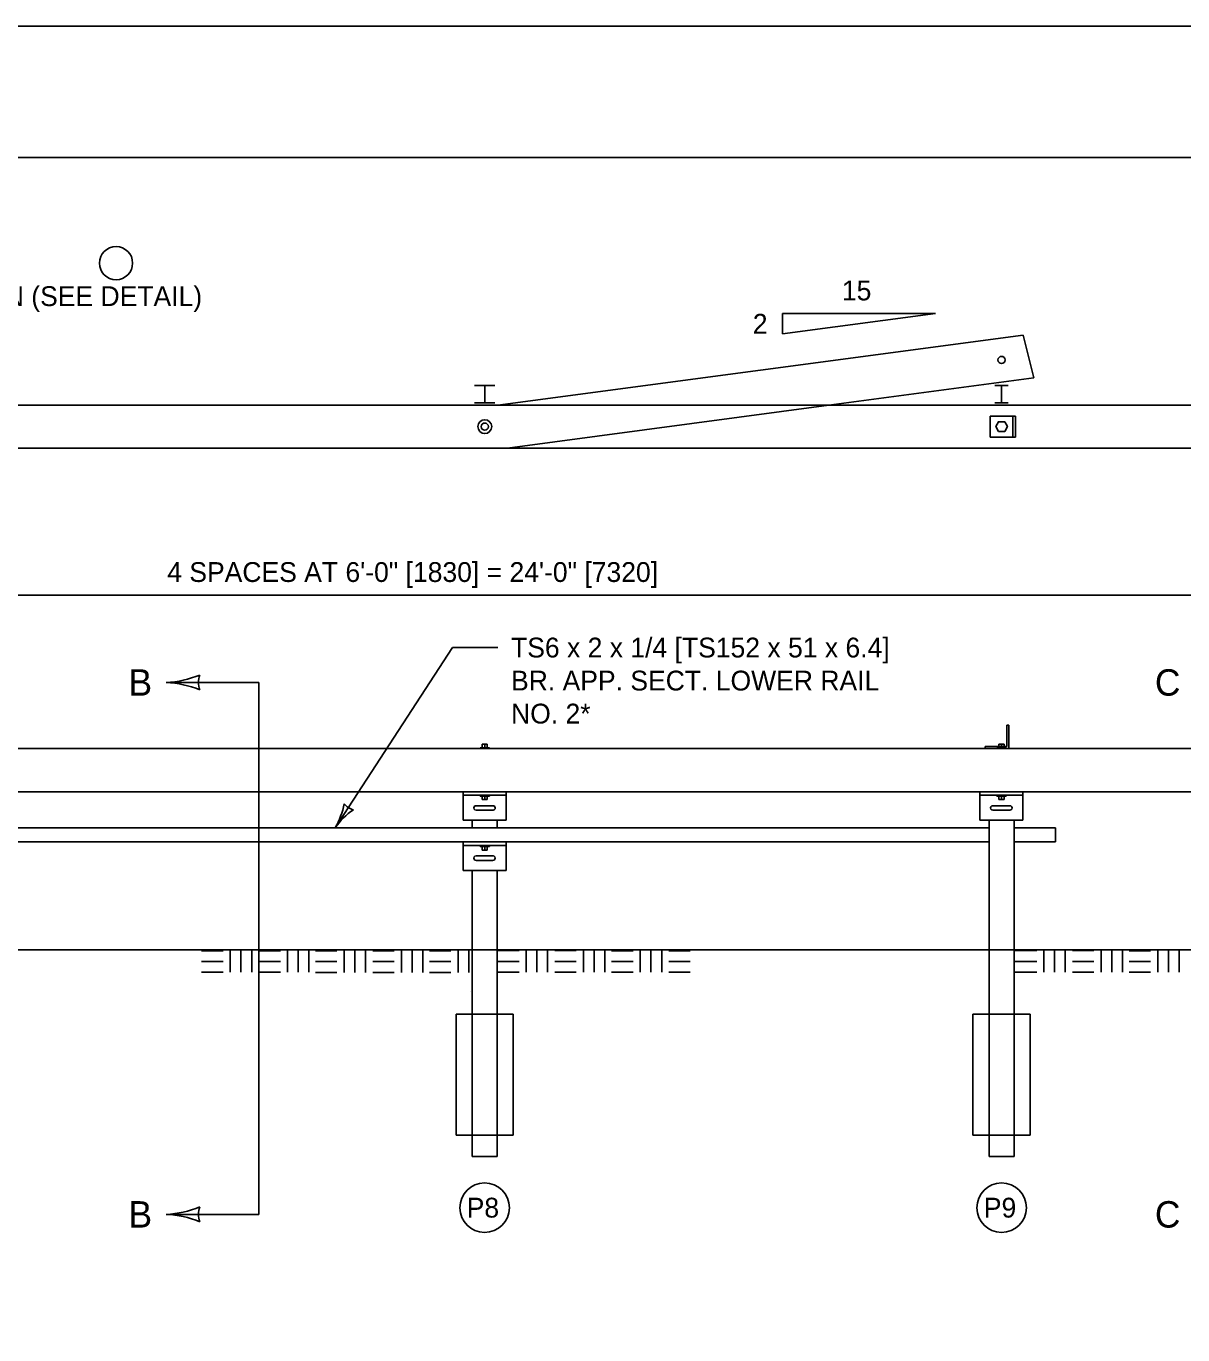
# Model space of a CAD drawing. Extents: x 49991.4 to 50021, y 49987.6 to 50011.4.
# Drawn here: x 50009.589 to 50013.09, y 49995.037 to 49998.999 of the extents above; entities that cross this region are included whole.
import ezdxf

# ---------------------------------------------------------------- set-up
doc = ezdxf.new("R2010")
doc.units = 0
for name, color, linetype in [('Level 1', 7, 'Continuous'), ('Level 2', 7, 'Continuous'), ('Level 3', 7, 'Continuous'), ('Level 4', 7, 'Continuous'), ('Level 6', 7, 'Continuous')]:
    doc.layers.add(name, color=color, linetype=linetype)

msp = doc.modelspace()

# ---------------------------------------------------------------- linework, layer by layer
at = {"layer": 'Level 1'}
for p, q in [((50011.0164, 49997.8514), (50012.6065, 49998.0634)), ((50012.6394, 49997.9343), (50012.6071, 49998.0636)), ((50012.0183, 49997.8514), (50012.6394, 49997.9343)), ((50010.9456, 49997.9109), (50011.0071, 49997.9109)), ((50010.9769, 49997.8585), (50010.9769, 49997.9109)), ((50012.5209, 49997.9109), (50012.5609, 49997.9109)), ((50012.5413, 49997.8585), (50012.5413, 49997.9109)), ((50001.743, 49997.8514), (50015.4519, 49997.8514)), ((50010.9456, 49997.8585), (50011.0071, 49997.8585)), ((50012.5209, 49997.8585), (50012.5609, 49997.8585)), ((50012.5067, 49997.818), (50012.5837, 49997.818)), ((50012.5068, 49997.7548), (50012.5068, 49997.818)), ((50012.5753, 49997.7548), (50012.5753, 49997.818)), ((50012.5839, 49997.7548), (50012.5839, 49997.818)), ((50012.5067, 49997.7548), (50012.5837, 49997.7548)), ((50001.743, 49997.7218), (50015.4519, 49997.7218)), ((50012.5574, 49996.8177), (50012.5574, 49996.8831)), ((50012.5574, 49996.8831), (50012.5633, 49996.8831)), ((50012.5633, 49996.8831), (50012.5633, 49996.8116)), ((50010.9688, 49996.825), (50010.9839, 49996.825)), ((50010.9688, 49996.825), (50010.9688, 49996.8144)), ((50010.9769, 49996.825), (50010.9769, 49996.8144)), ((50010.9839, 49996.825), (50010.9839, 49996.8144)), ((50012.4917, 49996.8118), (50012.4917, 49996.8177)), ((50012.4917, 49996.8177), (50012.5574, 49996.8177)), ((50012.5326, 49996.825), (50012.5494, 49996.825)), ((50012.5326, 49996.825), (50012.5326, 49996.8144)), ((50012.5413, 49996.825), (50012.5413, 49996.8144)), ((50012.5494, 49996.825), (50012.5494, 49996.8144)), ((50002.0298, 49996.8116), (50015.4519, 49996.8116)), ((50010.9439, 49996.8116), (50011.0087, 49996.8116)), ((50010.9625, 49996.8144), (50010.991, 49996.8144)), ((50010.9625, 49996.8116), (50010.9625, 49996.8144)), ((50010.991, 49996.8116), (50010.991, 49996.8144)), ((50012.5076, 49996.8116), (50012.5733, 49996.8116)), ((50012.5272, 49996.8144), (50012.5547, 49996.8144)), ((50012.5272, 49996.8116), (50012.5272, 49996.8144)), ((50012.5547, 49996.8116), (50012.5547, 49996.8144)), ((50002.0298, 49996.6812), (50015.4519, 49996.6812)), ((50010.9111, 49996.595), (50010.9111, 49996.6812)), ((50010.9111, 49996.6705), (50011.0416, 49996.6705)), ((50010.9625, 49996.6705), (50010.9625, 49996.6679)), ((50010.9625, 49996.6679), (50010.991, 49996.6679)), ((50010.9688, 49996.6572), (50010.9688, 49996.6679)), ((50010.9688, 49996.6572), (50010.9839, 49996.6572)), ((50010.9769, 49996.6572), (50010.9769, 49996.6679)), ((50010.9839, 49996.6572), (50010.9839, 49996.6679)), ((50010.991, 49996.6705), (50010.991, 49996.6679)), ((50011.0416, 49996.595), (50011.0416, 49996.6812)), ((50012.4757, 49996.595), (50012.4757, 49996.6812)), ((50012.4757, 49996.6705), (50012.6053, 49996.6705)), ((50012.5272, 49996.6705), (50012.5272, 49996.6679)), ((50012.5272, 49996.6679), (50012.5547, 49996.6679)), ((50012.5326, 49996.6572), (50012.5326, 49996.6679)), ((50012.5326, 49996.6572), (50012.5494, 49996.6572)), ((50012.5413, 49996.6572), (50012.5413, 49996.6679)), ((50012.5494, 49996.6572), (50012.5494, 49996.6679)), ((50012.5547, 49996.6705), (50012.5547, 49996.6679)), ((50012.6053, 49996.595), (50012.6053, 49996.6812)), ((50010.9498, 49996.6389), (50011.0021, 49996.6389)), ((50010.9506, 49996.6253), (50011.0023, 49996.6253)), ((50012.5144, 49996.6389), (50012.5667, 49996.6389)), ((50012.5153, 49996.6253), (50012.5659, 49996.6253)), ((50010.9111, 49996.595), (50011.0416, 49996.595)), ((50010.9386, 49996.5719), (50010.9386, 49996.5949)), ((50011.0142, 49996.5719), (50011.0142, 49996.5955)), ((50012.4757, 49996.595), (50012.6053, 49996.595)), ((50012.5032, 49996.2026), (50012.5032, 49996.595)), ((50012.5796, 49996.2026), (50012.5796, 49996.595)), ((50002.0449, 49996.5719), (50012.5032, 49996.5719)), ((50012.5796, 49996.5719), (50012.704, 49996.5719)), ((50012.704, 49996.5294), (50012.704, 49996.5719)), ((50007.0813, 49996.5294), (50012.5032, 49996.5294)), ((50010.9111, 49996.4422), (50010.9111, 49996.5294)), ((50010.9111, 49996.5187), (50011.0416, 49996.5187)), ((50010.9625, 49996.5187), (50010.9625, 49996.5152)), ((50010.9625, 49996.5152), (50010.991, 49996.5152)), ((50010.9688, 49996.5044), (50010.9688, 49996.5152)), ((50010.9688, 49996.5044), (50010.9839, 49996.5044)), ((50010.9769, 49996.5044), (50010.9769, 49996.5152)), ((50010.9839, 49996.5044), (50010.9839, 49996.5152)), ((50010.991, 49996.5187), (50010.991, 49996.5152)), ((50011.0416, 49996.4422), (50011.0416, 49996.5294)), ((50012.5796, 49996.5294), (50012.704, 49996.5294)), ((50010.9506, 49996.4868), (50011.0032, 49996.4868)), ((50010.9506, 49996.4732), (50011.0013, 49996.4732)), ((50010.9111, 49996.4422), (50011.0416, 49996.4422)), ((50010.9386, 49996.2026), (50010.9386, 49996.4422)), ((50011.0142, 49996.2026), (50011.0142, 49996.4428)), ((50001.5626, 49996.2026), (50015.4519, 49996.2026)), ((50010.1197, 49996.1996), (50010.1847, 49996.1996)), ((50010.2064, 49996.1346), (50010.2064, 49996.1996)), ((50010.2389, 49996.1346), (50010.2389, 49996.1996)), ((50010.2714, 49996.1346), (50010.2714, 49996.1996)), ((50010.293, 49996.1996), (50010.3581, 49996.1996)), ((50010.3798, 49996.1346), (50010.3798, 49996.1996)), ((50010.4122, 49996.1346), (50010.4122, 49996.1996)), ((50010.4447, 49996.1346), (50010.4447, 49996.1996)), ((50010.4645, 49996.1991), (50010.5295, 49996.1991)), ((50010.5512, 49996.1341), (50010.5512, 49996.1991)), ((50010.5837, 49996.1341), (50010.5837, 49996.1991)), ((50010.6162, 49996.1341), (50010.6162, 49996.1991)), ((50010.6378, 49996.1991), (50010.7029, 49996.1991)), ((50010.7246, 49996.1341), (50010.7246, 49996.1991)), ((50010.757, 49996.1341), (50010.757, 49996.1991)), ((50010.7895, 49996.1341), (50010.7895, 49996.1991)), ((50010.8092, 49996.1991), (50010.8742, 49996.1991)), ((50010.8959, 49996.1341), (50010.8959, 49996.1991)), ((50010.9284, 49996.1341), (50010.9284, 49996.1991)), ((50011.0155, 49996.2), (50011.0805, 49996.2)), ((50011.1022, 49996.135), (50011.1022, 49996.2)), ((50011.1347, 49996.135), (50011.1347, 49996.2)), ((50011.1672, 49996.135), (50011.1672, 49996.2)), ((50011.1888, 49996.2), (50011.2539, 49996.2)), ((50011.2756, 49996.135), (50011.2756, 49996.2)), ((50011.308, 49996.135), (50011.308, 49996.2)), ((50011.3405, 49996.135), (50011.3405, 49996.2)), ((50011.3607, 49996.1996), (50011.4257, 49996.1996)), ((50011.4474, 49996.1346), (50011.4474, 49996.1996)), ((50011.4799, 49996.1346), (50011.4799, 49996.1996)), ((50011.5124, 49996.1346), (50011.5124, 49996.1996)), ((50011.534, 49996.1996), (50011.5991, 49996.1996)), ((50012.5825, 49996.1999), (50012.6475, 49996.1999)), ((50012.6692, 49996.1349), (50012.6692, 49996.1999)), ((50012.7017, 49996.1349), (50012.7017, 49996.1999)), ((50012.7342, 49996.1349), (50012.7342, 49996.1999)), ((50012.7558, 49996.1999), (50012.8209, 49996.1999)), ((50012.8426, 49996.1349), (50012.8426, 49996.1999)), ((50012.875, 49996.1349), (50012.875, 49996.1999)), ((50012.9075, 49996.1349), (50012.9075, 49996.1999)), ((50012.9274, 49996.1995), (50012.9924, 49996.1995)), ((50013.0141, 49996.1345), (50013.0141, 49996.1995)), ((50013.0466, 49996.1345), (50013.0466, 49996.1995)), ((50013.0791, 49996.1345), (50013.0791, 49996.1995)), ((50010.1197, 49996.1671), (50010.1847, 49996.1671)), ((50010.293, 49996.1671), (50010.3581, 49996.1671)), ((50010.4645, 49996.1666), (50010.5295, 49996.1666)), ((50010.6378, 49996.1666), (50010.7029, 49996.1666)), ((50010.8092, 49996.1666), (50010.8742, 49996.1666)), ((50011.0155, 49996.1675), (50011.0805, 49996.1675)), ((50011.1888, 49996.1675), (50011.2539, 49996.1675)), ((50011.3607, 49996.1671), (50011.4257, 49996.1671)), ((50011.534, 49996.1671), (50011.5991, 49996.1671)), ((50012.5825, 49996.1674), (50012.6475, 49996.1674)), ((50012.7558, 49996.1674), (50012.8209, 49996.1674)), ((50012.9274, 49996.167), (50012.9924, 49996.167)), ((50010.1197, 49996.1346), (50010.1847, 49996.1346)), ((50010.293, 49996.1346), (50010.3581, 49996.1346)), ((50010.4645, 49996.1341), (50010.5295, 49996.1341)), ((50010.6378, 49996.1341), (50010.7029, 49996.1341)), ((50010.8092, 49996.1341), (50010.8742, 49996.1341)), ((50011.0155, 49996.135), (50011.0805, 49996.135)), ((50011.1888, 49996.135), (50011.2539, 49996.135)), ((50011.3607, 49996.1346), (50011.4257, 49996.1346)), ((50011.534, 49996.1346), (50011.5991, 49996.1346)), ((50012.5825, 49996.1349), (50012.6475, 49996.1349)), ((50012.7558, 49996.1349), (50012.8209, 49996.1349)), ((50012.9274, 49996.1345), (50012.9924, 49996.1345))]:
    msp.add_line(p, q, dxfattribs=at)
for points in [[(49999.3835, 49998.9992), (50016.7501, 49998.9992), (50016.7501, 49987.7988), (49999.3835, 49987.7988)], [(50012.5319, 49997.7716), (50012.5508, 49997.7716), (50012.559, 49997.7866), (50012.5508, 49997.8016), (50012.5319, 49997.8016), (50012.5237, 49997.7866)]]:
    msp.add_lwpolyline(points, close=True, dxfattribs=at)
for centre, radius in [((50012.5413, 49997.9885), 0.0109), ((50010.9769, 49997.7866), 0.0209), ((50010.9769, 49997.7866), 0.0109)]:
    msp.add_circle(centre, radius, dxfattribs=at)
for centre, start, end in [((50010.9503, 49996.6321), 86.0196, 273.7417), ((50011.0019, 49996.6321), 273.7413, 93.9804), ((50012.5149, 49996.6321), 86.0196, 273.9804), ((50012.5664, 49996.6321), 266.0196, 93.9804), ((50010.9503, 49996.48), 86.0196, 273.9804), ((50011.0019, 49996.48), 266.0196, 93.9804)]:
    msp.add_arc(centre, 0.00681, start, end, dxfattribs=at)
at = {"layer": 'Level 2'}
for centre, radius in [((50009.8607, 49998.2817), 0.0503), ((50010.9764, 49995.4216), 0.075), ((50012.5414, 49995.4216), 0.075)]:
    msp.add_circle(centre, radius, dxfattribs=at)
at = {"layer": 'Level 3'}
for p, q in [((50001.5626, 49998.6017), (50014.9504, 49998.6017)), ((50012.3411, 49998.1289), (50011.8785, 49998.0672)), ((50012.3411, 49998.1289), (50011.8785, 49998.1289)), ((50011.8785, 49998.1289), (50011.8785, 49998.0672)), ((50007.8468, 49997.2763), (50014.106, 49997.2763)), ((50010.5238, 49996.5719), (50010.8795, 49997.1177)), ((50011.0164, 49997.1177), (50010.8795, 49997.1177))]:
    msp.add_line(p, q, dxfattribs=at)
for centre, radius, start, end in [((50010.3226, 49996.6893), 0.233, 329.7366, 348.9865), ((50010.7049, 49996.443), 0.2223, 124.3653, 144.5488), ((50010.5938, 49996.6793), 0.0548, 219.0481, 254.7705)]:
    msp.add_arc(centre, radius, start, end, dxfattribs=at)
at = {"layer": 'Level 4'}
for p, q in [((50011.0461, 49997.7218), (50012.0183, 49997.8514)), ((50010.9386, 49995.5766), (50010.9386, 49996.2026)), ((50011.0142, 49995.5766), (50011.0142, 49996.2026)), ((50012.5032, 49995.5766), (50012.5032, 49996.2026)), ((50012.5796, 49995.5766), (50012.5796, 49996.2026)), ((50010.9333, 49996.0755), (50010.9333, 49996.0755)), ((50010.8898, 49996.0072), (50011.063, 49996.0072)), ((50010.8898, 49996.0072), (50010.8898, 49995.6414)), ((50011.063, 49995.6414), (50011.063, 49996.0072)), ((50012.4545, 49996.0072), (50012.6282, 49996.0072)), ((50012.4545, 49995.6414), (50012.4545, 49996.0072)), ((50012.6282, 49995.6414), (50012.6282, 49996.0072)), ((50010.8898, 49995.6414), (50011.063, 49995.6414)), ((50012.4545, 49995.6414), (50012.6282, 49995.6414)), ((50010.9386, 49995.5766), (50011.0142, 49995.5766)), ((50012.5032, 49995.5766), (50012.5796, 49995.5766))]:
    msp.add_line(p, q, dxfattribs=at)
at = {"layer": 'Level 6'}
for points in [[(50010.2925, 49997.012), (50010.0125, 49997.012)], [(50010.2925, 49997.012), (50010.2925, 49995.4014)], [(50010.2925, 49995.4014), (50010.0125, 49995.4014)]]:
    msp.add_lwpolyline(points, dxfattribs=at)
for centre, radius, start, end in [((50009.9972, 49997.3223), 0.3107, 272.8273, 292.0772), ((50010.1835, 49997.012), 0.073, 162.1388, 197.8612), ((50010.0003, 49996.7158), 0.2964, 67.456, 87.6395), ((50009.9972, 49995.7117), 0.3107, 272.8273, 292.0772), ((50010.0003, 49995.1052), 0.2964, 67.456, 87.6395), ((50010.1835, 49995.4014), 0.073, 162.1388, 197.8612)]:
    msp.add_arc(centre, radius, start, end, dxfattribs=at)

# ---------------------------------------------------------------- texts
at = {"layer": 'Level 2'}
for s, height, p in [('LOWER RAIL - TS6 x 2 [TS152 x 51] RAIL CONNECTION (SEE DETAIL)', 0.06, (50007.4997, 49998.1517)), ('15', 0.06, (50012.0579, 49998.1689)), ('2', 0.06, (50011.7882, 49998.0681)), ('4 SPACES AT 6\'-0" [1830] = 24\'-0" [7320]', 0.06, (50010.0156, 49997.3163)), ('TS6 x 2 x 1/4 [TS152 x 51 x 6.4] ', 0.06, (50011.0564, 49997.0877)), ('C', 0.08, (50013.0054, 49996.972)), ('B', 0.08, (50009.8985, 49996.972)), ('BR. APP. SECT. LOWER RAIL ', 0.06, (50011.0564, 49996.9877)), ('NO. 2*', 0.06, (50011.0564, 49996.8877)), ('B', 0.08, (50009.8985, 49995.3614)), ('P8', 0.06, (50010.9221, 49995.3917)), ('P9', 0.06, (50012.4876, 49995.3917)), ('C', 0.08, (50013.0054, 49995.3614))]:
    msp.add_text(s, height=height, dxfattribs=at).set_placement(p)

doc.saveas('drawing.dxf')
